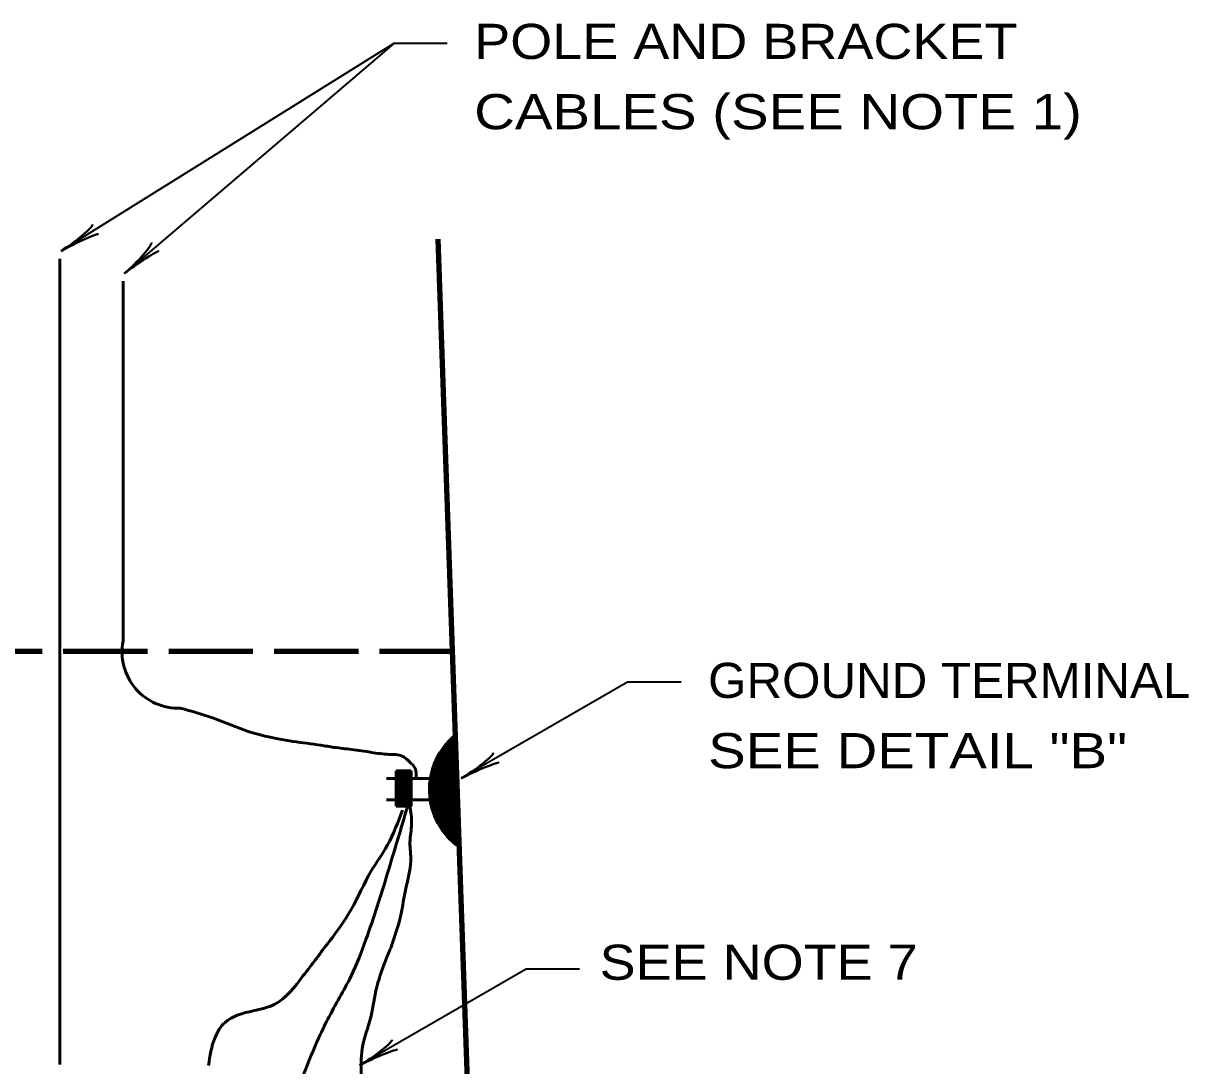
# Model space of a CAD drawing. Extents: x -153 to 527, y -247 to 194.
# Drawn here: x 102.3 to 185.2, y -124.2 to -50 of the extents above; entities that cross this region are included whole.
import ezdxf

# ---------------------------------------------------------------- set-up
doc = ezdxf.new("R2010")
doc.units = 0
doc.linetypes.add('LONG_DASHED', pattern=[7.5, 6, -1.5])
doc.layers.add('1', color=7, linetype='Continuous', lineweight=53)

msp = doc.modelspace()

# ---------------------------------------------------------------- linework, layer by layer
at = {"layer": '1', "lineweight": 35}
msp.add_line((128.66, -51.462), (109.49, -67.83), dxfattribs=at)
at = {"layer": '1', "lineweight": 90}
msp.add_line((134.641, -146.336), (131.815, -65.386), dxfattribs=at)
at = {"layer": '1'}
for p, q in [((104.89, -124.133), (104.89, -66.779)), ((109.39, -93.992), (109.39, -68.383)), ((133.186, -108.452), (132.837, -100.971)), ((132.919, -100.848), (133.227, -108.452)), ((128.823, -103.238), (128.823, -105.738)), ((128.823, -103.238), (129.89, -103.238)), ((128.823, -103.262), (129.89, -103.262)), ((128.823, -103.268), (129.89, -103.268)), ((128.823, -103.287), (129.89, -103.287)), ((128.823, -103.324), (129.89, -103.324)), ((128.823, -103.331), (129.89, -103.331)), ((128.823, -103.356), (129.89, -103.356)), ((128.823, -103.374), (129.89, -103.374)), ((128.823, -103.374), (129.89, -103.374)), ((128.823, -103.4), (129.89, -103.4)), ((128.823, -103.406), (129.89, -103.406)), ((128.823, -103.406), (129.89, -103.406)), ((128.823, -103.418), (129.89, -103.418)), ((128.823, -103.431), (129.89, -103.431)), ((128.823, -103.444), (129.89, -103.444)), ((128.823, -103.462), (129.89, -103.462)), ((128.823, -103.487), (129.89, -103.487)), ((128.823, -103.494), (129.89, -103.494)), ((128.823, -103.5), (129.89, -103.5)), ((128.823, -103.531), (129.89, -103.531)), ((128.823, -103.544), (129.89, -103.544)), ((128.823, -103.544), (129.89, -103.544)), ((128.823, -103.556), (129.89, -103.556)), ((128.823, -103.562), (129.89, -103.562)), ((128.823, -103.569), (129.89, -103.569)), ((128.823, -103.569), (129.89, -103.569)), ((128.823, -103.588), (129.89, -103.588)), ((128.823, -103.606), (129.89, -103.606)), ((128.823, -103.606), (129.89, -103.606)), ((128.823, -103.619), (129.89, -103.619)), ((128.823, -103.644), (129.89, -103.644)), ((128.823, -103.644), (129.89, -103.644)), ((128.823, -103.663), (129.89, -103.663)), ((128.823, -103.675), (129.89, -103.675)), ((128.823, -103.675), (129.89, -103.675)), ((129.89, -103.238), (129.89, -105.738)), ((131.254, -103.786), (128.131, -103.786)), ((128.823, -103.7), (129.89, -103.7)), ((128.823, -103.7), (129.89, -103.7)), ((128.823, -103.725), (129.89, -103.725)), ((128.823, -103.732), (129.89, -103.732)), ((128.823, -103.732), (129.89, -103.732)), ((128.823, -103.751), (129.89, -103.751)), ((128.823, -103.757), (129.89, -103.757)), ((128.823, -103.776), (129.89, -103.776)), ((128.823, -103.782), (129.89, -103.782)), ((128.823, -103.813), (129.89, -103.813)), ((128.823, -103.819), (129.89, -103.819)), ((128.823, -103.826), (129.89, -103.826)), ((128.823, -103.826), (129.89, -103.826)), ((128.823, -103.838), (129.89, -103.838)), ((128.823, -103.876), (129.89, -103.876)), ((128.823, -103.876), (129.89, -103.876)), ((128.823, -103.882), (129.89, -103.882)), ((128.823, -103.882), (129.89, -103.882)), ((128.823, -103.901), (129.89, -103.901)), ((128.823, -103.932), (129.89, -103.932)), ((128.823, -103.932), (129.89, -103.932)), ((128.823, -103.945), (129.89, -103.945)), ((128.823, -103.976), (129.89, -103.976)), ((128.823, -104.007), (129.89, -104.007)), ((128.823, -104.039), (129.89, -104.039)), ((128.823, -104.051), (129.89, -104.051)), ((128.823, -104.064), (129.89, -104.064)), ((128.823, -104.083), (129.89, -104.083)), ((128.823, -104.114), (129.89, -104.114)), ((128.823, -104.145), (129.89, -104.145)), ((128.823, -104.158), (129.89, -104.158)), ((128.823, -104.183), (129.89, -104.183)), ((128.823, -104.183), (129.89, -104.183)), ((128.823, -104.202), (129.89, -104.202)), ((128.823, -104.221), (129.89, -104.221)), ((128.823, -104.227), (129.89, -104.227)), ((128.823, -104.246), (129.89, -104.246)), ((128.823, -104.246), (129.89, -104.246)), ((128.823, -104.283), (129.89, -104.283)), ((128.823, -104.289), (129.89, -104.289)), ((128.823, -104.321), (129.89, -104.321)), ((128.823, -104.333), (129.89, -104.333)), ((128.823, -104.346), (129.89, -104.346)), ((128.823, -104.383), (129.89, -104.383)), ((128.823, -104.383), (129.89, -104.383)), ((128.823, -104.421), (129.89, -104.421)), ((128.823, -104.44), (129.89, -104.44)), ((128.823, -104.452), (129.89, -104.452)), ((128.823, -104.477), (129.89, -104.477)), ((128.823, -104.477), (129.89, -104.477)), ((128.823, -104.509), (129.89, -104.509)), ((131.244, -105.286), (128.131, -105.286)), ((128.823, -104.534), (129.89, -104.534)), ((128.823, -104.571), (129.89, -104.571)), ((128.823, -104.603), (129.89, -104.603)), ((128.823, -104.64), (129.89, -104.64)), ((128.823, -104.659), (129.89, -104.659)), ((128.823, -104.684), (129.89, -104.684)), ((128.823, -104.715), (129.89, -104.715)), ((128.823, -104.734), (129.89, -104.734)), ((128.823, -104.772), (129.89, -104.772)), ((128.823, -104.797), (129.89, -104.797)), ((128.823, -104.816), (129.89, -104.816)), ((128.823, -104.835), (129.89, -104.835)), ((128.823, -104.835), (129.89, -104.835)), ((128.823, -104.86), (129.89, -104.86)), ((128.823, -104.878), (129.89, -104.878)), ((128.823, -104.878), (129.89, -104.878)), ((128.823, -104.897), (129.89, -104.897)), ((128.823, -104.922), (129.89, -104.922)), ((128.823, -104.929), (129.89, -104.929)), ((128.823, -104.96), (129.89, -104.96)), ((128.823, -104.96), (129.89, -104.96)), ((128.823, -104.972), (129.89, -104.972)), ((128.823, -104.979), (129.89, -104.979)), ((128.823, -104.998), (129.89, -104.998)), ((128.823, -105.016), (129.89, -105.016)), ((128.823, -105.016), (129.89, -105.016)), ((128.823, -105.041), (129.89, -105.041)), ((128.823, -105.06), (129.89, -105.06)), ((128.823, -105.091), (129.89, -105.091)), ((128.823, -105.117), (129.89, -105.117)), ((128.823, -105.135), (129.89, -105.135)), ((128.823, -105.148), (129.89, -105.148)), ((128.823, -105.167), (129.89, -105.167)), ((128.823, -105.198), (129.89, -105.198)), ((128.823, -105.229), (129.89, -105.229)), ((128.823, -105.254), (129.89, -105.254)), ((128.823, -105.267), (129.89, -105.267)), ((128.823, -105.273), (129.89, -105.273)), ((128.823, -105.311), (129.89, -105.311)), ((128.823, -105.342), (129.89, -105.342)), ((128.823, -105.38), (129.89, -105.38)), ((128.823, -105.399), (129.89, -105.399)), ((128.823, -105.442), (129.89, -105.442)), ((128.823, -105.461), (129.89, -105.461)), ((128.823, -105.474), (129.89, -105.474)), ((128.823, -105.511), (129.89, -105.511)), ((128.823, -105.536), (129.89, -105.536)), ((128.823, -105.574), (129.89, -105.574)), ((128.823, -105.593), (129.89, -105.593)), ((128.823, -105.618), (129.89, -105.618)), ((128.823, -105.643), (129.89, -105.643)), ((128.823, -105.674), (129.89, -105.674)), ((128.823, -105.68), (129.89, -105.68)), ((128.823, -105.699), (129.89, -105.699)), ((128.823, -105.724), (129.89, -105.724)), ((128.823, -105.738), (129.89, -105.738))]:
    msp.add_line(p, q, dxfattribs=at)
at = {"layer": '1', "linetype": 'LONG_DASHED', "lineweight": 90}
msp.add_line((90.136, -94.723), (132.839, -94.723), dxfattribs=at)
at = {"layer": '1', "lineweight": 35}
for points in [[(132.458, -51.462), (128.66, -51.462), (104.99, -66.225)], [(149.105, -96.923), (145.306, -96.923), (133.459, -103.762)], [(141.883, -117.349), (138.085, -117.349), (126.238, -124.188)]]:
    msp.add_lwpolyline(points, dxfattribs=at)
at = {"layer": '1'}
for points in [[(132.734, -101.033), (133.104, -108.411), (132.652, -101.074), (133.022, -108.349), (132.569, -101.259), (132.939, -108.267), (132.446, -101.341), (132.837, -108.185), (132.487, -101.362), (132.734, -108.061), (132.343, -101.465), (132.631, -108.02), (132.323, -101.526), (132.528, -107.876), (133.289, -108.534), (132.405, -107.774), (132.2, -101.609), (132.857, -100.971), (132.241, -101.711), (132.426, -107.609)], [(132.302, -107.548), (132.117, -101.814), (132.302, -107.609), (132.035, -101.917), (132.22, -107.507), (132.508, -107.774)], [(132.138, -107.404), (131.85, -102.205), (132.035, -107.26), (131.747, -102.328), (131.953, -107.075), (131.686, -102.574), (131.85, -106.911), (131.583, -102.759), (131.747, -106.705), (131.46, -103.027), (131.645, -106.479), (131.398, -103.397), (131.562, -106.15), (131.336, -103.684), (131.48, -106.006), (131.254, -104.054), (131.377, -105.616), (131.501, -103.068)], [(132.467, -107.63), (132.158, -107.363), (131.953, -102.04), (132.158, -107.342)], [(131.521, -103.807), (131.254, -104.773), (131.521, -106.13), (131.891, -106.828), (132.076, -107.26)]]:
    msp.add_lwpolyline(points, dxfattribs=at)
for centre, radius, start, end in [((113.324, -94.765), 4.009, 168.87665, 271.96071), ((136.18, -104.569), 4.988, 128.68208, 235.31633)]:
    msp.add_arc(centre, radius, start, end, dxfattribs=at)
at = {"layer": '1', "lineweight": 40}
for centre, major_axis, ratio, start_param, end_param in [((105.77, -65.413), (-1.433, -1.078), 0.122415, 0.896353, 3.141593), ((105.77, -65.413), (-1.433, -1.078), 0.122415, 0.896353, 3.141593), ((106.053, -65.812), (1.583, 0.781), 0.07063, 6.282307, 8.559703), ((106.053, -65.812), (1.583, 0.781), 0.07063, 6.282307, 8.559703), ((110.141, -66.911), (-1.257, -1.278), 0.122415, 0.896353, 3.141593), ((110.141, -66.911), (-1.257, -1.278), 0.122415, 0.896353, 3.141593), ((110.48, -67.263), (1.45, 1.007), 0.07063, 6.282307, 8.559703), ((110.48, -67.263), (1.45, 1.007), 0.07063, 6.282307, 8.559703), ((134.266, -102.977), (-1.468, -1.028), 0.122415, 0.896353, 3.141593), ((134.535, -103.385), (1.609, 0.726), 0.07063, 6.282307, 8.559703), ((127.045, -123.403), (-1.468, -1.028), 0.122415, 0.896353, 3.141593), ((127.314, -123.811), (1.609, 0.726), 0.07063, 6.282307, 8.559703)]:
    msp.add_ellipse(centre, major_axis=major_axis, ratio=ratio, start_param=start_param, end_param=end_param, dxfattribs=at)
at = {"layer": '1'}
for points in [[(123.473, -101.404), (121.487, -101.133), (118.3, -100.425), (115.821, -99.48), (113.461, -98.772)], [(123.473, -101.404), (124.408, -101.56), (125.647, -101.708), (127.064, -101.915), (128.333, -102.062), (129.247, -102.18), (129.779, -102.593), (130.192, -103.065), (130.251, -103.715)], [(130.459, -105.326), (130.451, -105.314), (130.451, -105.292)], [(115.467, -124.208), (115.939, -122.202), (116.648, -121.139), (118.654, -120.313), (120.189, -119.841), (122.195, -117.835), (124.084, -115.356), (125.618, -113.113), (127.034, -110.398), (128.215, -108.51), (129.277, -106.031)], [(117.71, -152.418), (119.126, -151.71), (119.598, -150.057), (120.07, -147.815), (119.953, -145.336), (120.07, -142.385), (120.543, -138.726), (121.015, -135.067), (121.251, -131.998), (121.369, -127.867), (122.313, -124.68), (123.966, -120.903), (125.618, -117.835), (126.68, -115.238), (128.215, -110.517), (129.631, -105.795)], [(129.808, -105.707), (129.926, -107.005), (129.808, -108.304), (129.867, -109.661), (129.513, -111.609), (129.159, -113.497), (128.44, -115.843)], [(126.595, -130.184), (126.562, -127.602), (126.444, -126.363), (126.326, -124.474), (126.503, -122.527), (126.916, -121.169), (127.329, -119.163), (127.979, -116.979), (128.44, -115.843)]]:
    msp.add_spline(points, degree=3, dxfattribs=at)

# ---------------------------------------------------------------- texts
for s, width, p in [('POLE AND BRACKET', 1.15, (134.382, -52.561)), ('CABLES (SEE NOTE 1)', 1.2, (134.382, -57.561)), ('GROUND TERMINAL', 1.05, (151.033, -98.045)), ('SEE DETAIL "B"', 1.2, (151.033, -103.045)), ('SEE NOTE 7 ', 1.15, (143.306, -118.105))]:
    msp.add_text(s, height=2.5, dxfattribs=dict(at, width=width)).set_placement(p)

doc.saveas('drawing.dxf')
